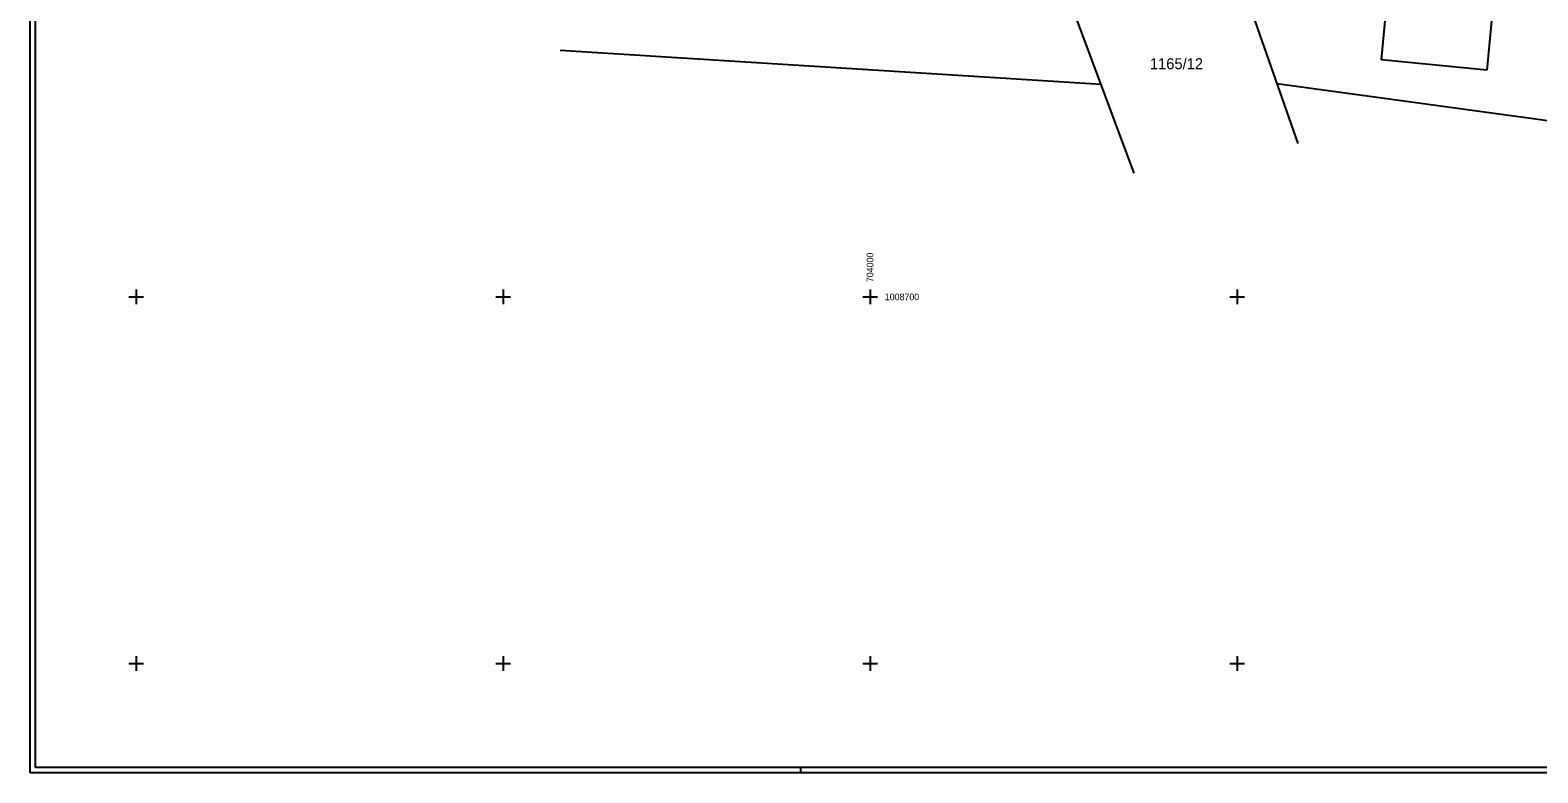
# Model space of a CAD drawing. Extents: x -704057 to -703795, y -1008732 to -1008584.
# Drawn here: x -704057.2 to -703954.5, y -1008732.5 to -1008681.8 of the extents above; entities that cross this region are included whole.
import ezdxf

# ---------------------------------------------------------------- set-up
doc = ezdxf.new("R2010")
doc.units = 0
for name, color, linetype in [('Z_hekt_sit', 7, 'Continuous'), ('Z_hekt_sit_popis', 7, 'Continuous'), ('Z_katastr_cisla_pozemkove', 7, 'Continuous'), ('Z_katastr_hranice', 7, 'Continuous'), ('Z_plotbox', 7, 'Continuous'), ('Z_ramecek_tisk', 7, 'Continuous')]:
    doc.layers.add(name, color=color, linetype=linetype)

msp = doc.modelspace()

# ---------------------------------------------------------------- linework, layer by layer
at = {"layer": 'Z_hekt_sit'}
for p, q in [((-704050, -1008699.5), (-704050, -1008700.5)), ((-704025, -1008699.5), (-704025, -1008700.5)), ((-704000, -1008699.5), (-704000, -1008700.5)), ((-703975, -1008699.5), (-703975, -1008700.5)), ((-704050.5, -1008700), (-704049.5, -1008700)), ((-704025.5, -1008700), (-704024.5, -1008700)), ((-704000.5, -1008700), (-703999.5, -1008700)), ((-703975.5, -1008700), (-703974.5, -1008700)), ((-704050, -1008724.5), (-704050, -1008725.5)), ((-704025, -1008724.5), (-704025, -1008725.5)), ((-704000, -1008724.5), (-704000, -1008725.5)), ((-703975, -1008724.5), (-703975, -1008725.5)), ((-704050.5, -1008725), (-704049.5, -1008725)), ((-704025.5, -1008725), (-704024.5, -1008725)), ((-704000.5, -1008725), (-703999.5, -1008725)), ((-703975.5, -1008725), (-703974.5, -1008725))]:
    msp.add_line(p, q, dxfattribs=at)
at = {"layer": 'Z_katastr_hranice'}
for p, q in [((-703981.08, -1008660.28), (-703970.86, -1008689.54)), ((-703956.49, -1008668.93), (-703957.98, -1008684.55)), ((-703982, -1008691.57), (-703988.54, -1008674.06)), ((-703965.17, -1008683.85), (-703964.68, -1008678.71)), ((-704021.13, -1008683.19), (-703984.26, -1008685.51)), ((-703957.98, -1008684.55), (-703965.17, -1008683.85)), ((-703972.28, -1008685.45), (-703894.62, -1008696.05))]:
    msp.add_line(p, q, dxfattribs=at)
at = {"layer": 'Z_plotbox'}
for p, q in [((-704057.23, -1008732.46), (-704057.23, -1008583.96)), ((-703794.73, -1008732.46), (-704057.23, -1008732.46)), ((-704004.73, -1008732.46), (-704004.73, -1008732.09))]:
    msp.add_line(p, q, dxfattribs=at)
at = {"layer": 'Z_ramecek_tisk'}
for p, q in [((-704056.86, -1008732.09), (-704056.86, -1008584.34)), ((-703795.11, -1008732.09), (-704056.86, -1008732.09))]:
    msp.add_line(p, q, dxfattribs=at)

# ---------------------------------------------------------------- texts
at = {"layer": 'Z_hekt_sit_popis'}
msp.add_text('704000', height=0.45, rotation=90, dxfattribs=at).set_placement((-703999.78, -1008699))
msp.add_text('1008700', height=0.45, dxfattribs=at).set_placement((-703999, -1008700.23))
at = {"layer": 'Z_katastr_cisla_pozemkove'}
msp.add_text('1165/12', height=0.75, dxfattribs=at).set_placement((-703980.94, -1008684.48))

doc.saveas('drawing.dxf')
